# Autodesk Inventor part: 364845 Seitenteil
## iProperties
Company: Mayer & Müller AG Schaltgeräte
Created: 2006-07
Part Number: 364845 Seitenteil
Material: 1.0120
Document SubType Name: Modeling
Designer: I.Baliuc
Manufacturer: Standard
Standards Organization: Custom
Description: Seitenteil, Trenner
Cost Center: 5,196 kg
Authority: 661896 mm^3
Density: 7.85 g/cm^3
HalbzeugNorm: DIN 174
Zweck: HSLT / HSE - Standardseite
Abmessung: Fl. 120x12-170
SaveDate: 2006-10-28
SaveTime: 20:23
TotalMass: 5,196 kg
TotalVolume: 661896 mm^3
Author: T.Messerschmitt
Revision Number: 364845
Keywords: 380125
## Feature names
1. Extrusion2
2. Bohrung_Ø13 [Hole]
3. Bohrung2 [Hole]
4. Bohrung3 [Hole]
5. Bohrung_M8_01 [Hole]
6. Bohrung_M8_02 [Hole]
7. Bohrung_M6 [Hole]
8. Bohrung_M5 [Hole]
9. Neue Bohrung (zusätzlich) [Rectangular Pattern]
